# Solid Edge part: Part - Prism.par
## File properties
Author: hhakima
Template: Normal.par
Last saved by: hhakima
Revision: 74
Application: Solid Edge
Material: Aluminum, 6061-T6
Face Style: Aluminum
Fill Style: ANSI38(Aluminum)
Virtual Style: Polished aluminum
Coef. of Thermal Exp: 2.3e-05
Thermal Conductivity: 180.0
Specific Heat: 920.0
Modulus of Elasticity: 68947570000.0
Poission's Ratio: 0.33
Yield Stress: 275790280.0
Ultimate Stress: 310264065.0
Elongation: 0.0
Density: 2712.000 kg/m^3
Accuracy: 0.990
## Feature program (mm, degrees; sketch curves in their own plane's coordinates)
sketch for "unnamed Protrusion 1" plane through (0, 0, 0) normal (0, -1, 0) x-axis (1, 0, 0)
  line (13.7575, 16.6928) -> (13.7575, -8.3072)
  line (13.7575, -8.3072) -> (-11.2425, -8.3072)
  line (-11.2425, -8.3072) -> (-11.2425, 16.6928)
  line (-11.2425, 16.6928) -> (13.7575, 16.6928)
extrude "unnamed Protrusion 1" add finite 25 along +normal
sketch for "ExtrudedCutout_3" plane through (-11.2425, 0, -8.3072) normal (0, -0.707107, -0.707107) x-axis (1, 0, 0)
extrude "ExtrudedCutout_3" cut finite 30 along -normal
sketch for "ExtrudedCutout_4" plane through (-1.9925, -25, 0.9428) normal (0, -1, 0) x-axis (1, 0, 0)
extrude "ExtrudedCutout_4" cut finite 16 along -normal
sketch for "ExtrudedProtrusion_6" #1 plane through (1.2575, -13.9142, -8.3072) normal (0, 0, -1) x-axis (0, -1, 0)
  line (-6.4142, 5) -> (-11.4142, 5)
  line (-11.4142, 5) -> (-11.4142, 10)
  line (-11.4142, 10) -> (-6.4142, 10)
  line (-6.4142, 10) -> (-6.4142, 5)
sketch for "ExtrudedProtrusion_6" #2 plane through (1.2575, -13.9142, -8.3072) normal (0, 0, -1) x-axis (0, -1, 0)
sketch for "ExtrudedProtrusion_6" #3 plane through (1.2575, -13.9142, -8.3072) normal (0, 0, -1) x-axis (0, -1, 0)
sketch for "ExtrudedProtrusion_6" #4 plane through (1.2575, -13.9142, -8.3072) normal (0, 0, -1) x-axis (0, -1, 0)
extrude "ExtrudedProtrusion_6" add finite 5 along +normal
mirror "unnamed Mirror 1" of "ExtrudedCutout_4" about plane through (-11.2425, -22.7003, -6.0075) normal (0, -0.707107, 0.707107)
extrude "unnamed Cutout 1" cut finite 16
sketch for "ExtrudedCutout_9" plane through (-11.2425, 0, -8.3072) normal (0, -0.707107, -0.707107) x-axis (1, 0, 0)
  line (29.3943, 36.7287) -> (29.3943, -5.0986)
  line (29.3943, -5.0986) -> (-8.577, -5.0986)
  line (-8.577, -5.0986) -> (-8.577, 36.7287)
  line (-8.577, 36.7287) -> (29.3943, 36.7287)
extrude "ExtrudedCutout_9" cut finite 23.95 along -normal
sketch for "ExtrudedCutout_12" plane through (1.2575, -12.1773, 3.8701) normal (0, 0.707107, 0.707107) x-axis (0, 0.707107, -0.707107)
extrude "ExtrudedCutout_12" cut finite 5 along -normal
sketch for "ExtrudedCutout_13" plane through (1.2575, -12.5, -8.3072) normal (0, 0, -1) x-axis (0, -1, 0)
extrude "ExtrudedCutout_13" cut finite 5 along -normal
sketch for "Hole_12" plane through (1.2575, -12.5, -13.3072) normal (0, 0, -1) x-axis (0, -1, 0)
hole "Hole_12" finite
sketch for "unnamed Hole 1" plane through (1.2575, -12.5, -13.3072) normal (0, 0, -1) x-axis (0, -1, 0)
hole "unnamed Hole 1" finite
sketch for "unnamed Hole 2" plane through (1.2575, -12.5, -13.3072) normal (0, 0, -1) x-axis (0, -1, 0)
  hole centre (-7.8, 7.8) bore radius 1.0065
hole "unnamed Hole 2" finite
sketch for "unnamed Hole 3" plane through (1.2575, -12.5, -13.3072) normal (0, 0, -1) x-axis (0, -1, 0)
hole "unnamed Hole 3" finite
sketch for "Hole_22" plane through (1.2575, -12.5, 4.1928) normal (0, 0.707107, 0.707107) x-axis (0, -0.707107, 0.707107)
hole "Hole_22" finite
sketch for "unnamed Hole 4" plane through (1.2575, -12.5, 4.1928) normal (0, 0.707107, 0.707107) x-axis (0, -0.707107, 0.707107)
  hole centre (9.5, 9.5) bore radius 1.0065
hole "unnamed Hole 4" finite
sketch for "unnamed Hole 5" plane through (1.2575, -12.5, 4.1928) normal (0, 0.707107, 0.707107) x-axis (0, -0.707107, 0.707107)
hole "unnamed Hole 5" finite
sketch for "unnamed Hole 6" plane through (1.2575, -12.5, 4.1928) normal (0, 0.707107, 0.707107) x-axis (0, -0.707107, 0.707107)
  hole centre (-9.5, -9.5) bore radius 1.0065
hole "unnamed Hole 6" finite
sketch for "Hole_25" plane through (1.2575, -12.5, 4.1928) normal (0, 0.707107, 0.707107) x-axis (0, 0.707107, -0.707107)
hole "Hole_25" diameter 3.175 finite
sketch for "unnamed Hole 7" plane through (1.2575, -12.5, 4.1928) normal (0, 0.707107, 0.707107) x-axis (0, 0.707107, -0.707107)
hole "unnamed Hole 7" finite
sketch for "unnamed Hole 8" plane through (1.2575, -12.5, 4.1928) normal (0, 0.707107, 0.707107) x-axis (0, 0.707107, -0.707107)
hole "unnamed Hole 8" finite
sketch for "unnamed Hole 9" plane through (1.2575, -12.5, 4.1928) normal (0, 0.707107, 0.707107) x-axis (0, 0.707107, -0.707107)
hole "unnamed Hole 9" finite
sketch for "unnamed Cutout 2" plane through (-6.2425, -5, -13.3072) normal (0, 0, -1) x-axis (0, -1, 0)
extrude "unnamed Cutout 2" cut to key point along -normal
sketch for "ExtrudedCutout_17" plane through (1.2575, -12.5, -8.3072) normal (0, 0, -1) x-axis (0, -1, 0)
  circle centre (7.5, -7.5) radius 8.75
extrude "ExtrudedCutout_17" cut finite 3 along -normal
sketch for "unnamed Cutout 3"
  line (3.5858, -10) -> (8.5858, -10)
  line (8.5858, -10) -> (8.5858, -5)
  line (8.5858, -5) -> (3.5858, -5)
  line (3.5858, -5) -> (3.5858, -10)
extrude "unnamed Cutout 3" cut finite 3
sketch for "Hole_20" plane through (13.7575, -12.5, 4.1928) normal (1, 0, 0) x-axis (0, 0, -1)
hole "Hole_20" finite
sketch for "unnamed Hole 10" plane through (13.7575, -12.5, 4.1928) normal (1, 0, 0) x-axis (0, 0, -1)
  hole centre (10, -2.5) bore radius 1.0065
  dimension (linear) = 10
  dimension (linear) = 10
hole "unnamed Hole 10" finite
mirror "unnamed Mirror 2" of "ExtrudedCutout_17" about plane through (-11.2425, -22.6393, -5.9465) normal (0, -0.707107, 0.707107)
pattern "unnamed Pattern 1" of "Hole_20", "unnamed Hole 10"
pattern "unnamed Pattern 2" of "Hole_12", "unnamed Hole 1", "unnamed Hole 2", "unnamed Hole 3"
pattern "unnamed Pattern 3" of "Hole_22", "unnamed Hole 4", "unnamed Hole 5", "unnamed Hole 6"
pattern "unnamed Pattern 4" of "Hole_25", "unnamed Hole 7", "unnamed Hole 8", "unnamed Hole 9"
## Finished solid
Body 1: solid body, 63 faces, 114 edges, 54 vertices.
  Faces by surface: plane 41, cylinder 22
  Edges by curve: line 67, circle 43, ellipse 2, intersection 2
Bounding box of the edges (mm): 25.000 x 22.500 x 27.500, from (-11.2425, -25, -13.3072) to (13.7575, -2.5, 14.1928).
Cylindrical faces by radius (mm): R1.0065 x10, R1.5875 x4, R3.3 x2, R5.25 x1, R6 x1, R8.75 x4
Planar faces by outward normal: +x 7, +y 3, +z 1, -x 5, -y 5, -z 10, oblique 10
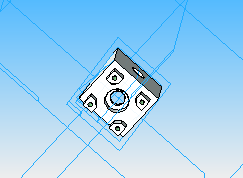
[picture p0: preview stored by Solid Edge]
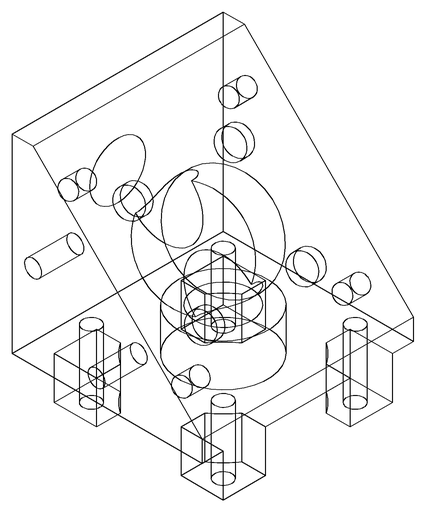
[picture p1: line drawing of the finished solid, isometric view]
